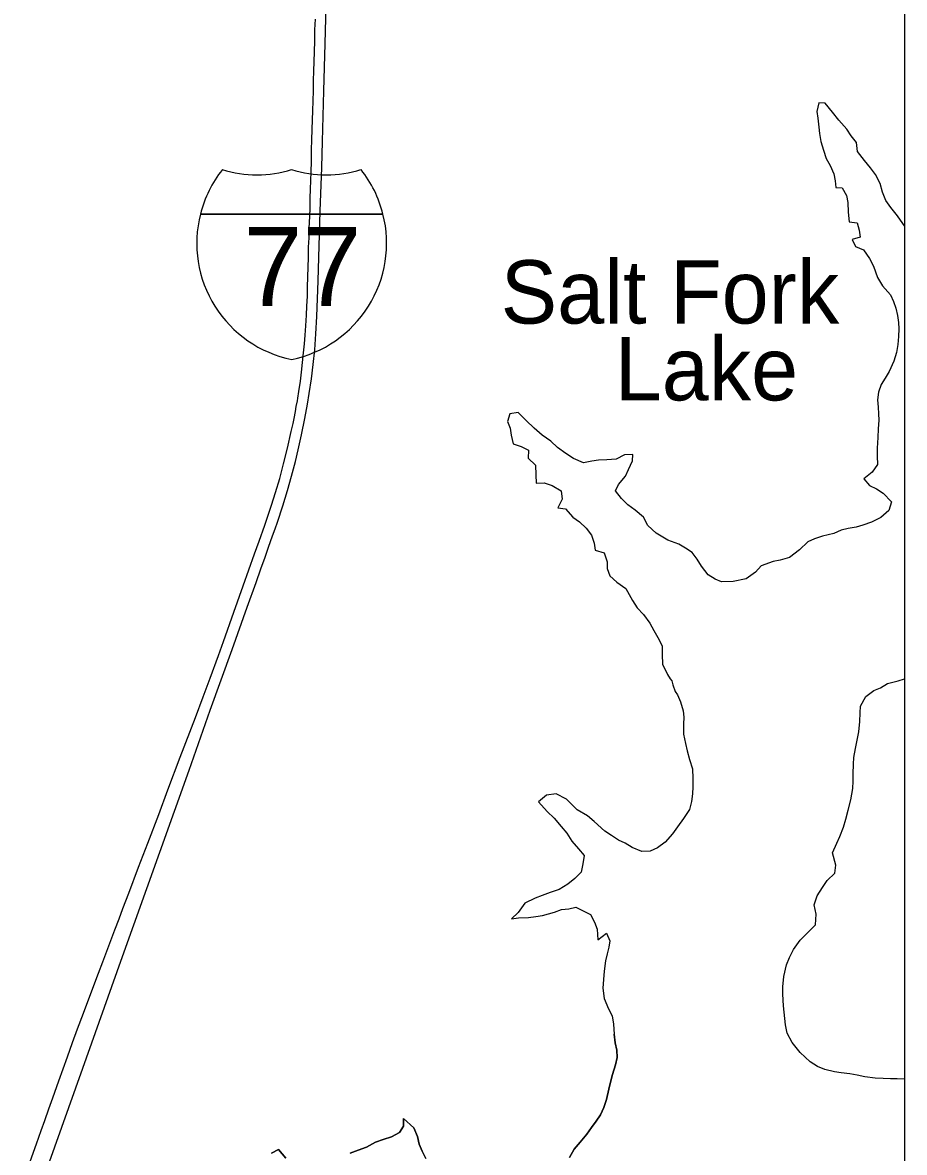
# Model space of a CAD drawing. Extents: x -12.1 to 34, y 0 to 22.
# Drawn here: x 9.352 to 10.59, y 15.871 to 17.456 of the extents above; entities that cross this region are included whole.
import ezdxf

# ---------------------------------------------------------------- set-up
doc = ezdxf.new("R2010")
doc.units = 0
for name, color, linetype in [('GM_X_Interstate_Route', 7, 'Continuous'), ('GM_X_Interstate_Shield', 7, 'Continuous'), ('GM_X_Major_Lake', 7, 'Continuous'), ('GM_X_Major_Lake_Text', 7, 'Continuous'), ('SH_Text', 7, 'Continuous')]:
    doc.layers.add(name, color=color, linetype=linetype)

msp = doc.modelspace()

# ---------------------------------------------------------------- linework, layer by layer
at = {"layer": 'GM_X_Interstate_Route'}
for points in [[(9.3581, 15.7681), (9.4368, 15.9891), (9.4902, 16.1389), (9.5085, 16.1898), (9.5447, 16.2919), (9.5654, 16.3494), (9.5859, 16.407), (9.6157, 16.491), (9.6466, 16.5764), (9.6675, 16.6357), (9.6799, 16.6702), (9.6866, 16.6895), (9.6926, 16.7059), (9.6974, 16.7197), (9.7031, 16.7355), (9.7067, 16.7457), (9.7098, 16.7548), (9.7175, 16.778), (9.724, 16.7991), (9.7298, 16.8193), (9.7352, 16.8401), (9.7391, 16.8565), (9.7437, 16.8776), (9.7483, 16.9004), (9.7521, 16.9204), (9.7546, 16.9353), (9.7577, 16.956), (9.7602, 16.9762), (9.7622, 16.9965), (9.764, 17.0191), (9.7653, 17.0435), (9.7672, 17.0936), (9.7701, 17.1913), (9.772, 17.2525), (9.773, 17.2891), (9.7749, 17.3601), (9.777, 17.4259), (9.7789, 17.4981)], [(9.3629, 15.8581), (9.3717, 15.8828), (9.3784, 15.9014), (9.3835, 15.9157), (9.3893, 15.9321), (9.3948, 15.9475), (9.4032, 15.971), (9.4153, 16.005), (9.4224, 16.0248), (9.4293, 16.0439), (9.4376, 16.0663), (9.4538, 16.1087), (9.4589, 16.1223), (9.4648, 16.1381), (9.4703, 16.1529), (9.4816, 16.1828), (9.4876, 16.1986), (9.4929, 16.2128), (9.5012, 16.2345), (9.5151, 16.271), (9.528, 16.3047), (9.5433, 16.3449), (9.5562, 16.3793), (9.5734, 16.425), (9.5948, 16.4807), (9.6058, 16.5097), (9.6155, 16.5362), (9.6271, 16.5678), (9.6341, 16.5877), (9.6486, 16.6288), (9.6617, 16.6656), (9.6778, 16.7105), (9.6842, 16.7282), (9.6923, 16.7509), (9.7017, 16.7785), (9.7074, 16.7963), (9.7131, 16.8161), (9.7184, 16.8368), (9.7241, 16.8586), (9.7294, 16.8823), (9.7318, 16.8931), (9.733, 16.8982), (9.7334, 16.9005), (9.7351, 16.9103), (9.7364, 16.9171), (9.7379, 16.9251), (9.7384, 16.9286), (9.7399, 16.9384), (9.7421, 16.9528), (9.7437, 16.9655), (9.7453, 16.9789), (9.7465, 16.9922), (9.7478, 17.005), (9.7487, 17.0172), (9.7498, 17.0305), (9.7507, 17.0451), (9.7512, 17.0579), (9.7519, 17.0718), (9.7521, 17.0852), (9.7527, 17.0986), (9.7529, 17.1132), (9.7535, 17.1259), (9.7537, 17.1405), (9.7543, 17.1539), (9.7545, 17.1673), (9.7553, 17.1835), (9.7556, 17.1952), (9.7559, 17.2091), (9.7565, 17.2225), (9.7567, 17.2336), (9.7571, 17.247), (9.7575, 17.2604), (9.7578, 17.2772), (9.7583, 17.2912), (9.7585, 17.3057), (9.7591, 17.3191), (9.7594, 17.3319), (9.76, 17.3459), (9.7604, 17.3599), (9.7606, 17.3733), (9.7612, 17.3884), (9.7613, 17.4), (9.7618, 17.4157), (9.7622, 17.4291), (9.7625, 17.4454), (9.7632, 17.4605)]]:
    msp.add_lwpolyline(points, dxfattribs=at)
at = {"layer": 'GM_X_Interstate_Shield'}
for p, q in [((9.6018, 17.1871), (9.858, 17.1871)), ((9.858, 17.1871), (9.6018, 17.1871)), ((9.858, 17.1871), (9.6018, 17.1871))]:
    msp.add_line(p, q, dxfattribs=at)
for centre, start, end in [((9.7632, 17.1463), 141.669, 165.8066), ((9.6812, 17.4087), 253.0091, 286.9909), ((9.7785, 17.4087), 253.0091, 286.9909), ((9.6966, 17.1463), 14.1934, 38.331), ((9.7632, 17.1463), 165.8066, 258.463), ((9.6966, 17.1463), 281.537, 14.1934)]:
    msp.add_arc(centre, 0.1665, start, end, dxfattribs=at)
at = {"layer": 'GM_X_Major_Lake'}
for points in [[(10.5897, 17.1708), (10.5875, 17.1738), (10.5799, 17.1848), (10.5706, 17.1961), (10.5638, 17.206), (10.5591, 17.218), (10.5558, 17.2301), (10.5493, 17.2425), (10.5421, 17.2521), (10.5339, 17.2623), (10.5238, 17.2747), (10.5227, 17.2875), (10.5148, 17.2967), (10.5087, 17.3062), (10.4979, 17.3189), (10.4889, 17.3302), (10.4785, 17.3426), (10.4697, 17.3433), (10.4669, 17.3311), (10.4684, 17.3216), (10.4696, 17.3088), (10.4704, 17.2999), (10.4726, 17.2889), (10.4762, 17.2768), (10.4799, 17.2651), (10.4856, 17.2552), (10.4907, 17.2435), (10.4926, 17.2335), (10.4937, 17.2243), (10.5026, 17.224), (10.5083, 17.213), (10.5102, 17.2031), (10.5107, 17.1899), (10.5122, 17.1764), (10.5236, 17.1747), (10.5261, 17.1644), (10.5276, 17.1548), (10.5163, 17.1512), (10.521, 17.1416), (10.5324, 17.1371), (10.5407, 17.1247), (10.5464, 17.1141), (10.5519, 17.0981), (10.5591, 17.0864), (10.5702, 17.0737), (10.5745, 17.0645), (10.5778, 17.0549), (10.58, 17.045), (10.5815, 17.035), (10.5819, 17.0261), (10.5816, 17.0155), (10.5803, 17.0041), (10.5786, 16.9927), (10.5748, 16.9806), (10.5682, 16.9663), (10.5629, 16.957), (10.557, 16.9481)], [(10.557, 16.9481), (10.5532, 16.9374), (10.5518, 16.9267), (10.553, 16.916), (10.5534, 16.9068), (10.5538, 16.8979), (10.5529, 16.8858), (10.5526, 16.8737), (10.5513, 16.8587), (10.5514, 16.8474), (10.5519, 16.836), (10.5445, 16.8249), (10.5328, 16.8159), (10.5407, 16.8064), (10.5504, 16.8015), (10.56, 16.7955), (10.5718, 16.7835), (10.568, 16.7714), (10.5564, 16.7613), (10.5436, 16.7548), (10.5316, 16.7508), (10.522, 16.7479), (10.5107, 16.746), (10.5008, 16.7438), (10.4909, 16.7391), (10.4749, 16.7351), (10.4636, 16.7314), (10.4544, 16.7274), (10.4424, 16.7163), (10.4286, 16.7052), (10.4152, 16.7015), (10.4056, 16.6997), (10.3886, 16.6938), (10.3809, 16.6849), (10.3678, 16.6755), (10.3494, 16.6718), (10.3331, 16.671), (10.3242, 16.6748), (10.3142, 16.6808), (10.3048, 16.6932), (10.2991, 16.7031), (10.2919, 16.7123), (10.2826, 16.7186), (10.273, 16.7239), (10.2577, 16.7298), (10.2413, 16.7396), (10.2298, 16.7502), (10.2237, 16.7619), (10.2119, 16.7718), (10.2015, 16.7792), (10.1926, 16.7883), (10.1843, 16.7989), (10.1885, 16.8079), (10.1984, 16.8193), (10.2026, 16.8286), (10.2081, 16.8407), (10.2084, 16.85), (10.1967, 16.8492), (10.185, 16.8434), (10.1723, 16.8422), (10.1606, 16.8418), (10.1513, 16.8406), (10.1396, 16.8381), (10.1254, 16.844), (10.1147, 16.851), (10.1029, 16.8598), (10.0936, 16.8686), (10.0815, 16.8771), (10.07, 16.8866), (10.0589, 16.8975), (10.0475, 16.9085), (10.0358, 16.9069), (10.0327, 16.8959), (10.0366, 16.8867), (10.0381, 16.8771), (10.0407, 16.865), (10.0518, 16.8608), (10.0621, 16.8559), (10.0618, 16.8446), (10.0719, 16.835), (10.0723, 16.8212), (10.0731, 16.8094), (10.0841, 16.8099), (10.0952, 16.8061), (10.108, 16.799), (10.1095, 16.7873), (10.1036, 16.7748), (10.1142, 16.7738), (10.1246, 16.7618), (10.1339, 16.7555), (10.1429, 16.7463), (10.1508, 16.7368), (10.1544, 16.7254), (10.1559, 16.7158), (10.1684, 16.712), (10.1724, 16.6993), (10.1728, 16.69), (10.1764, 16.6797), (10.1864, 16.6709), (10.1989, 16.6618), (10.2081, 16.6448)], [(10.2081, 16.6448), (10.2149, 16.6349), (10.2235, 16.6253), (10.2324, 16.6133), (10.2381, 16.6027), (10.2439, 16.5932), (10.25, 16.5815), (10.2497, 16.5694), (10.2501, 16.5559), (10.2573, 16.5414), (10.2609, 16.535), (10.2634, 16.5322), (10.2649, 16.5265), (10.2681, 16.5173), (10.2713, 16.5127), (10.2757, 16.5028), (10.2793, 16.4904), (10.2801, 16.4812), (10.2798, 16.4716), (10.2795, 16.4574), (10.2824, 16.4443), (10.285, 16.434), (10.2882, 16.4219), (10.2922, 16.4088), (10.2927, 16.3953), (10.2928, 16.3836), (10.2925, 16.3736), (10.2911, 16.363), (10.288, 16.3519), (10.2799, 16.3394), (10.2715, 16.3273), (10.2645, 16.3177), (10.2539, 16.3059), (10.243, 16.298), (10.2331, 16.2933), (10.2211, 16.2928), (10.2076, 16.2984), (10.198, 16.3044), (10.1887, 16.3089), (10.1788, 16.3153), (10.1695, 16.3216), (10.1545, 16.335), (10.1449, 16.3431), (10.1307, 16.3515), (10.1154, 16.3663), (10.1011, 16.374), (10.0877, 16.3721), (10.0761, 16.3625), (10.0885, 16.3491), (10.0982, 16.3395), (10.1082, 16.3279), (10.116, 16.3184), (10.1232, 16.3074), (10.1325, 16.2965), (10.1403, 16.2873), (10.1386, 16.2755), (10.1359, 16.2638), (10.1271, 16.2549), (10.1176, 16.247), (10.1052, 16.2394), (10.0928, 16.2354), (10.0812, 16.2311), (10.0716, 16.2274), (10.0572, 16.2202), (10.0477, 16.2074), (10.0382, 16.1984), (10.0481, 16.1999), (10.0623, 16.2004), (10.0725, 16.2015), (10.0817, 16.203), (10.0987, 16.2078), (10.1086, 16.2114), (10.1189, 16.2125), (10.1288, 16.2147), (10.1391, 16.2095), (10.1494, 16.2046), (10.1548, 16.1936), (10.1584, 16.184), (10.1595, 16.1691), (10.1719, 16.1781), (10.1762, 16.1678), (10.1748, 16.1589), (10.1728, 16.1493), (10.1704, 16.1394), (10.1683, 16.1248), (10.1674, 16.1131), (10.1667, 16.101), (10.1682, 16.0868), (10.1747, 16.0723), (10.1794, 16.0623), (10.1816, 16.0506), (10.1824, 16.0368)], [(10.5897, 15.9737), (10.5796, 15.9739), (10.5704, 15.9739), (10.5598, 15.9745), (10.5485, 15.9748), (10.5343, 15.9768), (10.5233, 15.9789), (10.513, 15.9809), (10.5009, 15.9826), (10.4914, 15.984), (10.4782, 15.9871), (10.4679, 15.9913), (10.4573, 15.9976), (10.4433, 16.011), (10.4323, 16.0251), (10.4251, 16.0382), (10.4229, 16.0499), (10.4202, 16.0762), (10.4191, 16.0929), (10.4193, 16.1032), (10.4207, 16.1177), (10.4241, 16.1341), (10.4283, 16.1444), (10.4342, 16.1555), (10.4434, 16.1687), (10.4539, 16.1787), (10.4648, 16.1898), (10.4658, 16.2051), (10.4632, 16.2179), (10.4674, 16.2307), (10.4747, 16.2424), (10.4811, 16.2524), (10.492, 16.2625), (10.4933, 16.2735), (10.4886, 16.2912), (10.4949, 16.3044), (10.4991, 16.3137), (10.5043, 16.3269), (10.5074, 16.3382), (10.5109, 16.3507), (10.5147, 16.3653), (10.5174, 16.3813), (10.5177, 16.3916), (10.5176, 16.4019), (10.5182, 16.4154), (10.5189, 16.4246), (10.5209, 16.4374), (10.5237, 16.4513), (10.5257, 16.4609), (10.5271, 16.4751), (10.5277, 16.4872), (10.5283, 16.4968), (10.5357, 16.5104), (10.5466, 16.5186), (10.5561, 16.5226), (10.566, 16.5287), (10.5809, 16.5324), (10.5897, 16.5352)], [(10.1824, 16.0368), (10.1839, 16.0244), (10.1861, 16.0144), (10.1865, 16.0041), (10.1841, 15.9938), (10.1799, 15.9799), (10.1772, 15.9693), (10.1751, 15.9593), (10.1717, 15.9451), (10.1679, 15.9337), (10.1633, 15.9233), (10.157, 15.9144), (10.1507, 15.9055), (10.144, 15.8965), (10.1349, 15.8851), (10.1261, 15.8751), (10.1198, 15.8637)], [(10.1198, 15.8637), (10.1261, 15.8751), (10.1349, 15.8851), (10.144, 15.8965), (10.1507, 15.9055), (10.157, 15.9144), (10.1633, 15.9233), (10.1679, 15.9337), (10.1717, 15.9451), (10.1751, 15.9593), (10.1772, 15.9693), (10.1799, 15.9799), (10.1841, 15.9938), (10.1865, 16.0041), (10.1861, 16.0144), (10.1839, 16.0244), (10.1824, 16.0368)], [(9.9182, 15.8622), (9.9128, 15.8724), (9.9088, 15.8824), (9.9066, 15.893), (9.9012, 15.9054), (9.887, 15.9184), (9.8867, 15.9078), (9.8814, 15.8989), (9.8698, 15.8927), (9.8585, 15.8891), (9.8475, 15.8851), (9.8348, 15.8783), (9.8232, 15.8739), (9.8118, 15.8696)], [(9.8118, 15.8696), (9.8232, 15.8739), (9.8348, 15.8783), (9.8475, 15.8851), (9.8585, 15.8891), (9.8698, 15.8927), (9.8814, 15.8989), (9.8867, 15.9078), (9.887, 15.9184), (9.9012, 15.9054), (9.9066, 15.893), (9.9088, 15.8824), (9.9128, 15.8724), (9.9182, 15.8622)], [(9.7219, 15.8628), (9.7115, 15.8748), (9.7017, 15.8698)], [(9.7017, 15.8698), (9.7115, 15.8748), (9.7219, 15.8628)]]:
    msp.add_lwpolyline(points, dxfattribs=at)
at = {"layer": 'SH_Text'}
msp.add_lwpolyline([(2.8817, 20.3063), (10.5897, 20.3063), (10.5897, 10.9773), (2.8817, 10.9773)], close=True, dxfattribs=at)

# ---------------------------------------------------------------- texts
at = {"layer": 'GM_X_Interstate_Shield'}
msp.add_text('77', height=0.11097, dxfattribs=at).set_placement((9.6625, 17.0581))
at = {"layer": 'GM_X_Major_Lake_Text'}
for s, rotation, p in [('Salt Fork', 0.0035, (10.0232, 17.0335)), ('Lake', 0.0018, (10.1832, 16.9257))]:
    msp.add_text(s, height=0.08878, rotation=rotation, dxfattribs=at).set_placement(p)

doc.saveas('drawing.dxf')
